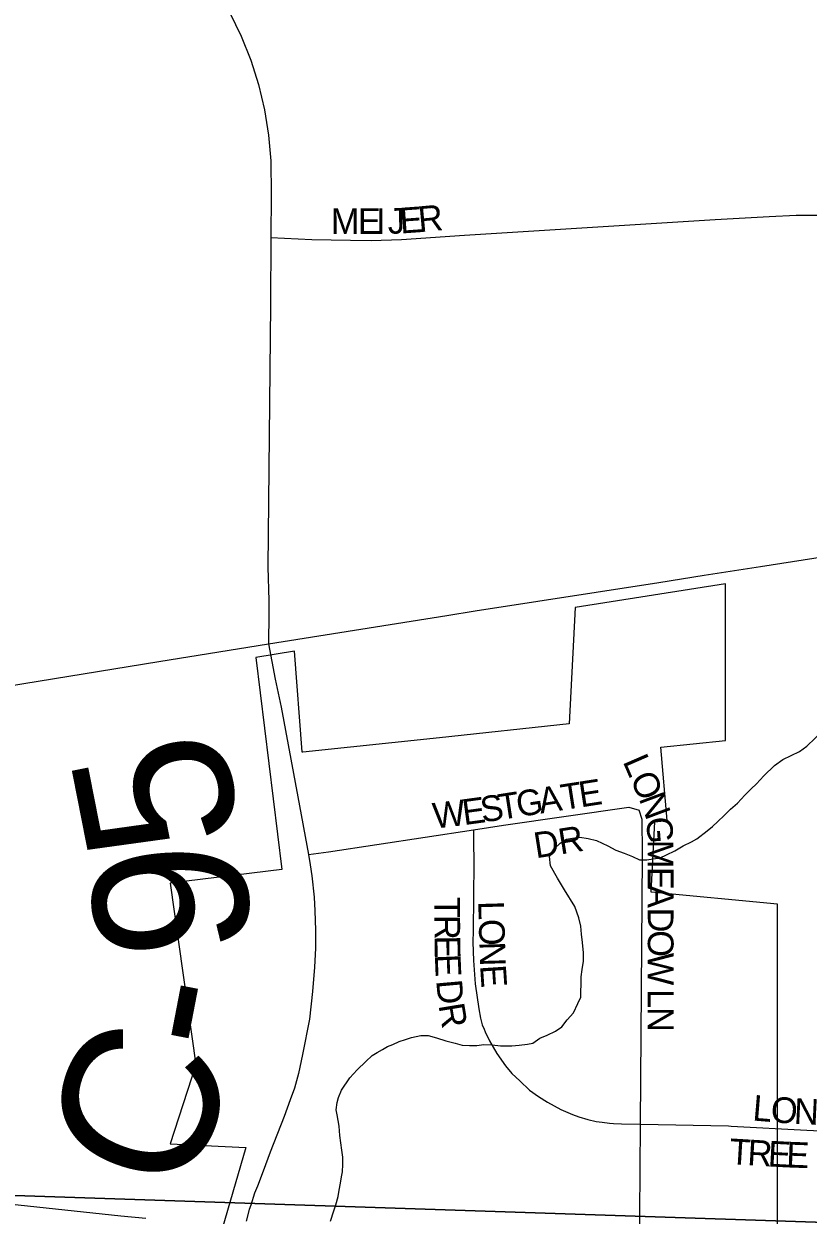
# Model space of a CAD drawing. Extents: x 1587405 to 1714697, y 1028970 to 1155083.
# Drawn here: x 1662922 to 1664447, y 1113302 to 1115620 of the extents above; entities that cross this region are included whole.
import ezdxf

# ---------------------------------------------------------------- set-up
doc = ezdxf.new("R2010")
doc.units = 0
for name, color, linetype in [('GM_X_City_Street', 7, 'Continuous'), ('GM_X_City_Street_Text', 7, 'Continuous'), ('GM_X_Corporation', 7, 'Continuous'), ('GM_X_County_Road', 7, 'Continuous'), ('GM_X_County_Road_Text', 7, 'Continuous'), ('GM_X_Minor_River', 7, 'Continuous'), ('GM_X_Section', 7, 'Continuous'), ('GM_X_Township_Subdivision', 7, 'Continuous'), ('GM_X_Township_Subdivision_Text', 7, 'Continuous'), ('GM_X_US_Route', 7, 'Continuous')]:
    doc.layers.add(name, color=color, linetype=linetype)

msp = doc.modelspace()

# ---------------------------------------------------------------- linework, layer by layer
at = {"layer": 'GM_X_City_Street'}
for points in [[(1663200, 1115807.9), (1663238.7, 1115765.4), (1663269.4, 1115725.8), (1663297.4, 1115684.3), (1663322.5, 1115641), (1663344.4, 1115595.9), (1663363, 1115549.4), (1663378.1, 1115501.6), (1663389.7, 1115452.8), (1663397.7, 1115403.3), (1663401.9, 1115353.4), (1663403, 1115287.3), (1663402.3, 1115204)], [(1663402.3, 1115204), (1663482.1, 1115200.2), (1663557, 1115198.8), (1663597.2, 1115198.5), (1663656, 1115200.5), (1663778.5, 1115208.5), (1664266.5, 1115239.1), (1664371.5, 1115245.1), (1664424.2, 1115247.7), (1664481.7, 1115247.8), (1665221.1, 1115234), (1665335.9, 1115234), (1665432.6, 1115233.1), (1665459.1, 1115232.3)], [(1663402.3, 1115204), (1663401.3, 1115073.2), (1663396.4, 1114563), (1663398.3, 1114497.6), (1663398.1, 1114472.7), (1663397.8, 1114413.4)], [(1663397.8, 1114413.4), (1663410.5, 1114344.6)], [(1664292.3, 1113475.4), (1664297.4, 1113475.3), (1664444.7, 1113467.1), (1664470.9, 1113466.2)], [(1662790.9, 1113354.9), (1662855.2, 1113327.6), (1663110.4, 1113300.7), (1663158.9, 1113296)], [(1663363, 1113321.5), (1663360.1, 1113313.2), (1663353.9, 1113290.4)], [(1664121.6, 1113208.7), (1664120.2, 1113222.3), (1664119.2, 1113245.9), (1664119.6, 1113302.7)]]:
    msp.add_lwpolyline(points, dxfattribs=at)
at = {"layer": 'GM_X_Corporation'}
msp.add_lwpolyline([(1664387.6, 1113182), (1664387.4, 1113906.7), (1664142, 1113930.6), (1664149.1, 1114067.4), (1664173, 1114069.9), (1664160.5, 1114212.4), (1664286.2, 1114225.7), (1664286.2, 1114530.4), (1663994.3, 1114484.2), (1663982.4, 1114258), (1663730, 1114230.6), (1663464.2, 1114202.5), (1663464, 1114202.5), (1663463.9, 1114202.5), (1663463.8, 1114202.5), (1663463.7, 1114202.6), (1663463.6, 1114202.6), (1663463.5, 1114202.7), (1663463.4, 1114202.8), (1663463.4, 1114202.8), (1663463.3, 1114202.9), (1663463.2, 1114203), (1663463.2, 1114203.1), (1663463.2, 1114203.2), (1663463.1, 1114203.3), (1663463.1, 1114203.4), (1663447.9, 1114399), (1663372.7, 1114387.2), (1663423.5, 1113974.5), (1663206.3, 1113947.7), (1663256, 1113594.2), (1663206.1, 1113440.7), (1663353.3, 1113433.6), (1663282.4, 1113188.6)], dxfattribs=at)
at = {"layer": 'GM_X_County_Road'}
for points in [[(1663410.5, 1114344.6), (1663421.9, 1114290.5), (1663454.5, 1114116), (1663475.2, 1114003.7)], [(1663475.2, 1114003.7), (1663478.6, 1113983.4), (1663481.6, 1113961.9), (1663486.2, 1113920.9), (1663487.9, 1113894.3), (1663488.8, 1113856.7), (1663488.8, 1113821.6), (1663486.7, 1113784.5), (1663483, 1113737.1), (1663477.1, 1113683.5), (1663463.6, 1113614.6), (1663456, 1113577.4), (1663448.1, 1113549.1), (1663439.9, 1113526), (1663427.7, 1113493.8), (1663400.9, 1113424.7), (1663387, 1113387.7), (1663376.2, 1113358.1), (1663370.4, 1113344.4), (1663363, 1113321.5)]]:
    msp.add_lwpolyline(points, dxfattribs=at)
at = {"layer": 'GM_X_Minor_River'}
for points in [[(1664019.2, 1114034.9), (1664035.3, 1114030.7), (1664057.3, 1114020.4), (1664073.3, 1114012.1), (1664089.3, 1114005.9), (1664105.4, 1113999.6), (1664119.4, 1113993.4), (1664133.5, 1113993.2), (1664145.6, 1113995.1), (1664159.7, 1113996.9), (1664171.9, 1114002.8), (1664188.1, 1114010.6), (1664204.3, 1114020.4), (1664220.5, 1114028.3), (1664230.7, 1114034.1), (1664251, 1114050), (1664261.2, 1114057.8), (1664271.4, 1114067.8), (1664283.7, 1114079.7), (1664295.9, 1114091.6), (1664310.1, 1114103.4), (1664324.4, 1114119.3), (1664336.7, 1114131.2), (1664346.9, 1114141.1), (1664361.2, 1114157), (1664381.6, 1114176.8), (1664397.8, 1114188.6), (1664414.1, 1114196.5), (1664430.3, 1114204.3), (1664444.5, 1114214.1), (1664477.1, 1114245.8)], [(1663518.2, 1113290.2), (1663524.5, 1113310.2), (1663528.7, 1113322.2), (1663532.9, 1113338.2), (1663535.1, 1113350.2), (1663537.3, 1113364.3), (1663539.4, 1113376.3), (1663541.6, 1113386.3), (1663541.8, 1113400.4), (1663541.9, 1113414.4), (1663540.1, 1113428.5), (1663538.3, 1113442.6), (1663536.4, 1113456.7), (1663534.7, 1113474.8), (1663530.9, 1113496.9), (1663529, 1113507), (1663531.2, 1113521.1), (1663533.4, 1113531.1), (1663539.6, 1113545), (1663556, 1113568.9), (1663570.3, 1113584.8), (1663586.6, 1113600.7), (1663598.9, 1113612.6), (1663609, 1113618.5), (1663619.2, 1113624.4), (1663629.3, 1113630.2), (1663639.4, 1113634.1), (1663651.6, 1113640), (1663663.7, 1113643.8), (1663675.8, 1113647.7), (1663694, 1113651.5), (1663708.1, 1113651.3), (1663724.2, 1113647.1), (1663742.2, 1113640.8), (1663760.3, 1113636.6), (1663774.4, 1113632.4), (1663788.5, 1113632.2), (1663802.5, 1113632), (1663816.7, 1113633.8), (1663832.8, 1113633.6), (1663848.9, 1113631.4), (1663871, 1113631.1), (1663885.2, 1113632.9), (1663901.3, 1113634.7), (1663911.4, 1113636.6), (1663925.6, 1113646.4), (1663939.8, 1113652.3), (1663956, 1113660.1), (1663968.2, 1113668), (1663978.4, 1113681.9), (1663990.7, 1113695.8), (1663999, 1113713.8), (1664005.2, 1113725.8), (1664005.3, 1113737.8), (1664005.5, 1113749.8), (1664005.7, 1113765.9), (1664007.9, 1113779.9), (1664010.1, 1113796), (1664010.3, 1113812.1), (1664008.6, 1113832.2), (1664006.7, 1113848.3), (1664004.9, 1113864.4), (1664001.1, 1113880.5), (1663993.3, 1113902.7), (1663973.6, 1113935.1), (1663959.8, 1113957.4), (1663946, 1113981.6), (1663944.2, 1113999.7), (1663952.5, 1114013.7), (1663964.7, 1114025.6), (1663976.9, 1114033.5), (1663989, 1114035.3), (1664003.1, 1114037.1), (1664019.2, 1114034.9)]]:
    msp.add_lwpolyline(points, dxfattribs=at)
at = {"layer": 'GM_X_Section'}
for points in [[(1661639.2, 1118644.5), (1667042.5, 1118475.3), (1666972.8, 1113204.7), (1661579.6, 1113384)], [(1666972.8, 1113204.7), (1666899, 1107940.3), (1661543.6, 1108095.1), (1661579.6, 1113384)]]:
    msp.add_lwpolyline(points, close=True, dxfattribs=at)
at = {"layer": 'GM_X_Township_Subdivision'}
for points in [[(1663796.2, 1114051.9), (1663854.5, 1114060.9), (1664098.6, 1114095.7), (1664118.4, 1114089.6)], [(1664120.9, 1113479.1), (1664124.8, 1114001.2), (1664124.9, 1114006.7), (1664124.7, 1114071.5), (1664118.4, 1114089.6)], [(1663475.2, 1114003.7), (1663514.4, 1114008.6), (1663796.2, 1114051.9)], [(1663796.2, 1114051.9), (1663796.6, 1114029.5), (1663797.2, 1113987.1), (1663795.9, 1113855.2), (1663795.3, 1113833.2), (1663796.3, 1113797.3), (1663799.8, 1113751.7), (1663806.4, 1113703.2), (1663809.8, 1113685.3), (1663813.4, 1113672), (1663816.8, 1113663.5)], [(1663816.8, 1113663.5), (1663818.7, 1113658.9), (1663827.2, 1113640.8), (1663842, 1113616.5), (1663858.4, 1113592.2), (1663871, 1113577.5), (1663886.6, 1113563.1), (1663905.4, 1113545.4), (1663922.9, 1113532.9), (1663940.4, 1113521.9), (1663966.1, 1113507.7), (1663989, 1113497.9), (1664001, 1113493.3), (1664018.6, 1113487.9), (1664034.9, 1113484.1), (1664046.7, 1113482.5), (1664061.1, 1113481), (1664068.5, 1113480.5), (1664084.1, 1113479.9), (1664120.9, 1113479.1)], [(1664119.6, 1113302.7), (1664120.9, 1113479.1)], [(1664120.9, 1113479.1), (1664292.3, 1113475.4)]]:
    msp.add_lwpolyline(points, dxfattribs=at)
at = {"layer": 'GM_X_US_Route'}
for points in [[(1664354.6, 1114564.1), (1664657.1, 1114611.6), (1664829.7, 1114638.8)], [(1664245.1, 1114547), (1664354.6, 1114564.1)], [(1663744.3, 1114468.7), (1663799.8, 1114477.6), (1664156.7, 1114533.1), (1664245.1, 1114547)], [(1663397.8, 1114413.4), (1663744.3, 1114468.7)], [(1660563.4, 1113938.9), (1660568.6, 1113939.8), (1660722.5, 1113965.9), (1661563.4, 1114114.4), (1661741.5, 1114143.9), (1662009.2, 1114186.5), (1662422.2, 1114255.1), (1662713.9, 1114302.3), (1663183.9, 1114379.3), (1663397.8, 1114413.4)]]:
    msp.add_lwpolyline(points, dxfattribs=at)

# ---------------------------------------------------------------- texts
at = {"layer": 'GM_X_City_Street_Text'}
for s, rotation, p in [('M', 0.0546, (1663518.8, 1115211)), ('E', 0.0273, (1663571.6, 1115211.1)), ('I', 0.0587, (1663606.8, 1115211.1)), ('J', 1.2451, (1663629.9, 1115211.2)), ('E', 4.0928, (1663654.6, 1115211.8)), ('R', 5.1615, (1663690.7, 1115214.4)), ('L', 355.2954, (1664338, 1113486.2)), ('O', 355.3307, (1664373.1, 1113483.3)), ('N', 357.3243, (1664418.8, 1113479.6)), ('T', 356.5549, (1664293, 1113401.3)), ('R', 356.5907, (1664328.1, 1113399.2)), ('E', 357.0141, (1664368.1, 1113396.8)), ('E', 357.8429, (1664404, 1113394.9))]:
    msp.add_text(s, height=50, rotation=rotation, dxfattribs=at).set_placement(p)
at = {"layer": 'GM_X_County_Road_Text'}
for s, rotation, p in [('5', 101.1417, (1663346.1, 1114037.9)), ('9', 93.8434, (1663363.8, 1113813.6)), ('-', 79.1334, (1663335.6, 1113610)), ('C', 69.7497, (1663236.6, 1113328.9))]:
    msp.add_text(s, height=300, rotation=rotation, dxfattribs=at).set_placement(p)
at = {"layer": 'GM_X_Township_Subdivision_Text'}
for s, rotation, p in [('L', 293.4964, (1664086.1, 1114184.7)), ('O', 293.4742, (1664100.2, 1114152.4)), ('T', 8.816, (1663970.2, 1114089.8)), ('E', 8.8064, (1664005, 1114095.2)), ('S', 8.7278, (1663813.6, 1114065.6)), ('T', 8.8276, (1663848.5, 1114070.9)), ('G', 8.8226, (1663883.3, 1114076.3)), ('A', 8.8226, (1663926.7, 1114083.1)), ('N', 290.5023, (1664117.4, 1114112.7)), ('W', 6.7747, (1663720.1, 1114053.8)), ('E', 7.762, (1663777.8, 1114060.7)), ('G', 274.3317, (1664132, 1114075.2)), ('DR', 8.9785, (1663917.8, 1113996.1)), ('M', 270.0364, (1664135.3, 1114032.3)), ('E', 270, (1664135.4, 1113979.5)), ('A', 269.9928, (1664135.4, 1113944.3)), ('T', 270, (1663720.3, 1113921.3)), ('L', 271.667, (1663805.4, 1113912.7)), ('D', 269.9928, (1664135.4, 1113900.3)), ('R', 270.1849, (1663720.3, 1113885.9)), ('O', 271.6722, (1663806.4, 1113877.5)), ('E', 270.9592, (1663720.4, 1113845.6)), ('O', 269.9928, (1664135.4, 1113856.3)), ('N', 271.6722, (1663807.7, 1113833.5)), ('E', 272.3045, (1663721, 1113809.1)), ('W', 269.9988, (1664135.4, 1113812.3)), ('E', 273.768, (1663809.1, 1113787.6)), ('D', 275.04, (1663723.7, 1113758.2)), ('L', 269.9956, (1664135.4, 1113741.9)), ('R', 279.2977, (1663728.1, 1113710.5)), ('N', 269.9928, (1664135.4, 1113706.7))]:
    msp.add_text(s, height=50, rotation=rotation, dxfattribs=at).set_placement(p)

doc.saveas('drawing.dxf')
